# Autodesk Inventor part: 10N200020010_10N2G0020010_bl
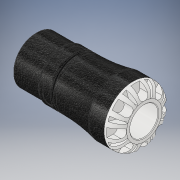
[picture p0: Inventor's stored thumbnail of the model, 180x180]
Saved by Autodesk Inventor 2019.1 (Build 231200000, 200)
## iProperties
Created: 2016-12
Part Number: 10N200020010_10N2G0020010_bl
Material: PVC-Piping
Description: PLASSON MALE ADAPTOR 20X1" SERIES 1
Document SubType Name: Modeling
Designer: KIM
Mass: 61.7504 g
Surface Area: 140.097 cm^2
Volume: 44.1074 cm^3
Density: 1.4 g/cm^3
Appearance: Black Cast
Author: KIM
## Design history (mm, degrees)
derived "10N20.ipt"
feature "Solid1::10N20.ipt" dims "ScaleForDerivedMember" = 10
tag "TaggingFeature1"
body "Solid1"
other parameters: "d0" = 77 [user parameter], "d1" = 18.9 [user parameter], "d3" = 25 [user parameter], "d4" = 41 [user parameter], "d6" = 45 [user parameter], "d8" = 34.85 [user parameter], "d13" = 6.4 [user parameter], "d14" = 6.4 [user parameter], "d15" = 0 [user parameter], "d17" = 360 deg [user parameter], "d19" = 8 deg [user parameter], "d20" = 0.4 [user parameter], "d21" = 0.4 [user parameter], "d22" = 8 deg [user parameter], "d24" = 0 [user parameter], "d26" = 360 deg [user parameter], "d32" = 0.925 [user parameter], "d33" = 4.1 [user parameter], "d34" = 33.249 [user parameter], "d35" = 2.5 [user parameter], "d38" = 19 [user parameter], "d39" = 0.99747 [user parameter], "d42" = 7 [user parameter], "d43" = 4.6 [user parameter], "d45" = 12.544 [user parameter], "d46" = 0 [user parameter], "d59" = 360 deg [user parameter], "d61" = 5.95 [user parameter], "d62" = 0.4 [user parameter], "d64" = 0 [user parameter], "d65" = 0.41 [user parameter], "d69" = 2 [user parameter], "d70" = 1.155 [user parameter], "d71" = 3 [user parameter], "d73" = 1 [user parameter], "E_" = 41 [user parameter], "H_" = 77 [user parameter], "l_" = 45 [user parameter], "R_" = 33.249 [user parameter], "l_2" = 19 [user parameter], "d9" = 8 [user parameter], "d11" = 41 [user parameter], "d12" = 25 [user parameter]
